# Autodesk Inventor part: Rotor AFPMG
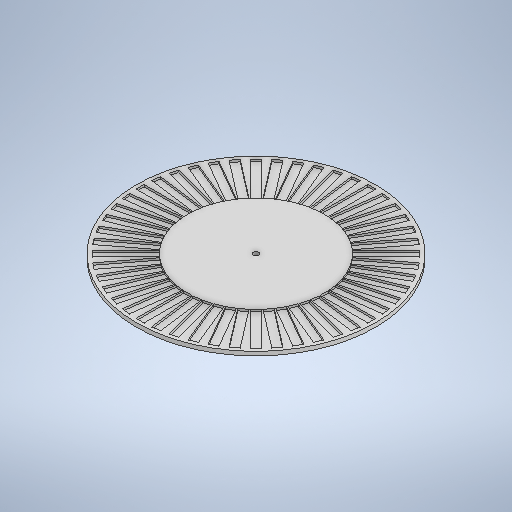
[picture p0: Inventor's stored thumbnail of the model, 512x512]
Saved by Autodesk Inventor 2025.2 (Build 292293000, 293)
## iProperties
Created: 2025-03
Part Number: Rotor AFPMG
Material: Generic
Document SubType Name: Modeling
Designer: bensa
Density: 1 g/cm^3
Appearance: Default
Author: bensa
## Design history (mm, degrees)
sketch "Sketch1"
  geometry: C1 r 150 at (0, 0); 1 further point
  constraints: 1 centre point, 1 coincident
  dimensions: "d0" = 300 diameter of C1
extrude "Extrusion1" new body sketch "Sketch1" distance "d1" = 5; taper "d2" = 0 deg
sketch "Sketch2"
  geometry: L1 (-114.512, -15.076)-(116.488, -15.076); L2 (-111.564, -29.894)-(119.436, -29.894); L3 (84.116, 16.117)-(143.603, 23.949); L4 (143.603, 23.949)-(144.908, 14.034); L5 (144.908, 14.034)-(85.421, 6.203); L6 (85.421, 6.203)-(84.116, 16.117); L7 (84.116, 16.117)-(144.908, 14.034); L8 (143.603, 23.949)-(85.421, 6.203); L9 (81.293, 26.959)-(139.248, 42.488); L10 (139.248, 42.488)-(141.836, 32.829); L11 (141.836, 32.829)-(83.881, 17.299); L12 (83.881, 17.299)-(81.293, 26.959); L13 (81.293, 26.959)-(141.836, 32.829); L14 (139.248, 42.488)-(83.881, 17.299); 1 further point
  constraints: 28 end point, 4 parallel, 2 horizontal, 2 perpendicular
  dimensions: "d7" = 60 distance of L3.start L3.end; "d8" = 10 distance of L3.end L4.end; "d9" = 60 distance of L9.start L9.end; "d10" = 10 distance of L9.end L10.end
sketch "Sketch3"
  geometry: L1 (-106.708, -44.2)-(124.292, -44.2); L2 (80.905, 28.1)-(136.338, 51.061); L3 (136.338, 51.061)-(132.511, 60.3); L4 (132.511, 60.3)-(77.078, 37.339); L5 (77.078, 37.339)-(80.905, 28.1); L6 (80.905, 28.1)-(132.511, 60.3); L7 (136.338, 51.061)-(77.078, 37.339); L8 (-100.026, -57.75)-(130.974, -57.75); L9 (76.545, 38.42)-(128.507, 68.42); L10 (128.507, 68.42)-(123.507, 77.08); L11 (123.507, 77.08)-(71.545, 47.08); L12 (71.545, 47.08)-(76.545, 38.42); L13 (76.545, 38.42)-(123.507, 77.08); L14 (128.507, 68.42)-(71.545, 47.08); L15 (-91.632, -70.312)-(139.368, -70.312); L16 (70.876, 48.082)-(118.477, 84.608); L17 (118.477, 84.608)-(112.389, 92.542); L18 (112.389, 92.542)-(64.788, 56.016); L19 (64.788, 56.016)-(70.876, 48.082); L20 (70.876, 48.082)-(112.389, 92.542); L21 (118.477, 84.608)-(64.788, 56.016); L22 (-81.671, -81.671)-(149.329, -81.671); L23 (63.993, 56.922)-(106.42, 99.349); L24 (106.42, 99.349)-(99.349, 106.42); L25 (99.349, 106.42)-(56.922, 63.993); L26 (56.922, 63.993)-(63.993, 56.922); L27 (63.993, 56.922)-(99.349, 106.42); L28 (106.42, 99.349)-(56.922, 63.993); L29 (-70.312, -91.632)-(160.688, -91.632); L30 (48.082, 70.876)-(84.608, 118.477); L31 (84.608, 118.477)-(92.542, 112.389); L32 (92.542, 112.389)-(56.016, 64.788); L33 (56.016, 64.788)-(48.082, 70.876); L34 (48.082, 70.876)-(92.542, 112.389); L35 (84.608, 118.477)-(56.016, 64.788); L36 (-57.75, -100.026)-(173.25, -100.026); L37 (47.08, 71.545)-(77.08, 123.507); L38 (77.08, 123.507)-(68.42, 128.507); L39 (68.42, 128.507)-(38.42, 76.545); L40 (38.42, 76.545)-(47.08, 71.545); L41 (47.08, 71.545)-(68.42, 128.507); L42 (77.08, 123.507)-(38.42, 76.545); L43 (-44.2, -106.708)-(186.8, -106.708); L44 (37.339, 77.078)-(60.3, 132.511); L45 (60.3, 132.511)-(51.061, 136.338); L46 (51.061, 136.338)-(28.1, 80.905); L47 (28.1, 80.905)-(37.339, 77.078); L48 (37.339, 77.078)-(51.061, 136.338); L49 (60.3, 132.511)-(28.1, 80.905); L50 (-29.894, -111.564)-(201.106, -111.564); L51 (17.299, 83.881)-(32.829, 141.836); L52 (32.829, 141.836)-(42.488, 139.248); L53 (42.488, 139.248)-(26.959, 81.293); L54 (26.959, 81.293)-(17.299, 83.881); L55 (17.299, 83.881)-(42.488, 139.248); L56 (32.829, 141.836)-(26.959, 81.293); L57 (-15.076, -114.512)-(215.924, -114.512); L58 (6.203, 85.421)-(14.034, 144.908); L59 (14.034, 144.908)-(23.949, 143.603); L60 (23.949, 143.603)-(16.117, 84.116); L61 (16.117, 84.116)-(6.203, 85.421); L62 (6.203, 85.421)-(23.949, 143.603); L63 (14.034, 144.908)-(16.117, 84.116); L64 (5, 85.5)-(5, 145.5)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; C1 r 150 at (0, 0); C2 r 150 at (0, 0); A1 r 150 centre (0, 0) between (150, 0) and (-150, 0) reference; 10 further points
  constraints: 328 end point, 32 parallel, 26 midpoint, 16 perpendicular, 12 horizontal, 2 centre point, 1 collinear, 1 point on circle, 2 other
  dimensions: "d13" = 60 distance of L2.start L2.end; "d14" = 10 distance of L3.end L2.end; "d17" = 60 distance of L9.start L9.end; "d18" = 10 distance of L10.end L9.end; "d21" = 60 distance of L16.start L16.end; "d22" = 10 distance of L17.end L16.end; "d25" = 60 distance of L23.start L23.end; "d26" = 10 distance of L24.end L23.end; "d29" = 60 distance of L30.start L30.end; "d30" = 10 distance of L30.end L31.end; "d33" = 60 distance of L37.start L37.end; "d34" = 10 distance of L38.end L37.end; "d37" = 60 distance of L44.start L44.end; "d38" = 10 distance of L45.end L44.end; "d41" = 60 distance of L51.start L51.end; "d42" = 10 distance of L51.end L52.end; "d45" = 60 distance of L58.start L58.end; "d46" = 10 distance of L58.end L59.end; "d48" = 60 distance of L64.start L64.end; "d49" = 10 distance of L65.end L64.end; "d52" = 60 distance of L126.start L126.end; "d53" = 10 distance of L127.end L126.end; "d56" = 60 distance of L133.start L133.end; "d57" = 10 distance of L133.end L134.end; "d59" = 60 distance of L140.start L140.end; "d60" = 10 distance of L140.end L141.end; "d61" = 60 distance of L147.start L147.end; "d62" = 10 distance of L148.end L147.end; "d63" = 60 distance of L153.start L153.end; "d64" = 10 distance of L153.end L154.end; "d65" = 60 distance of L159.start L159.end; "d66" = 10 distance of L159.end L160.end
sketch "Sketch4"
  geometry: L1 (0, 0)-(115.5, 0); L2 (-143.603, -23.949)-(-84.116, -16.117); L3 (-84.116, -16.117)-(-85.421, -6.203); L4 (-85.421, -6.203)-(-144.908, -14.034); L5 (-144.908, -14.034)-(-143.603, -23.949); L6 (-143.603, -23.949)-(-85.421, -6.203); L7 (-84.116, -16.117)-(-144.908, -14.034); L8 (0, 0)-(115.5, 0); L9 (-141.836, -32.829)-(-83.881, -17.299); L10 (-83.881, -17.299)-(-81.293, -26.959); L11 (-81.293, -26.959)-(-139.248, -42.488); L12 (-139.248, -42.488)-(-141.836, -32.829); L13 (-141.836, -32.829)-(-81.293, -26.959); L14 (-83.881, -17.299)-(-139.248, -42.488); L15 (0, 0)-(115.5, 0); L16 (-136.338, -51.061)-(-80.905, -28.1); L17 (-80.905, -28.1)-(-77.078, -37.339); L18 (-77.078, -37.339)-(-132.511, -60.3); L19 (-132.511, -60.3)-(-136.338, -51.061); L20 (-136.338, -51.061)-(-77.078, -37.339); L21 (-80.905, -28.1)-(-132.511, -60.3); L22 (0, 0)-(115.5, 0); L23 (-123.507, -77.08)-(-71.545, -47.08); L24 (-71.545, -47.08)-(-76.545, -38.42); L25 (-76.545, -38.42)-(-128.507, -68.42); L26 (-128.507, -68.42)-(-123.507, -77.08); L27 (-123.507, -77.08)-(-76.545, -38.42); L28 (-71.545, -47.08)-(-128.507, -68.42); L29 (0, 0)-(115.5, 0); L30 (-112.389, -92.542)-(-64.788, -56.016); L31 (-64.788, -56.016)-(-70.876, -48.082); L32 (-70.876, -48.082)-(-118.477, -84.608); L33 (-118.477, -84.608)-(-112.389, -92.542); L34 (-112.389, -92.542)-(-70.876, -48.082); L35 (-64.788, -56.016)-(-118.477, -84.608); L36 (0, 0)-(115.5, 0); L37 (-106.42, -99.349)-(-63.993, -56.922); L38 (-63.993, -56.922)-(-56.922, -63.993); L39 (-56.922, -63.993)-(-99.349, -106.42); L40 (-99.349, -106.42)-(-106.42, -99.349); L41 (-106.42, -99.349)-(-56.922, -63.993); L42 (-63.993, -56.922)-(-99.349, -106.42); L43 (0, 0)-(115.5, 0); L44 (-92.542, -112.389)-(-56.016, -64.788); L45 (-56.016, -64.788)-(-48.082, -70.876); L46 (-48.082, -70.876)-(-84.608, -118.477); L47 (-84.608, -118.477)-(-92.542, -112.389); L48 (-92.542, -112.389)-(-48.082, -70.876); L49 (-56.016, -64.788)-(-84.608, -118.477); L50 (0, 0)-(115.5, 0); L51 (-77.08, -123.507)-(-47.08, -71.545); L52 (-47.08, -71.545)-(-38.42, -76.545); L53 (-38.42, -76.545)-(-68.42, -128.507); L54 (-68.42, -128.507)-(-77.08, -123.507); L55 (-77.08, -123.507)-(-38.42, -76.545); L56 (-47.08, -71.545)-(-68.42, -128.507); L57 (0, 0)-(115.5, 0); L58 (-60.3, -132.511)-(-37.339, -77.078); L59 (-37.339, -77.078)-(-28.1, -80.905); L60 (-28.1, -80.905)-(-51.061, -136.338); L61 (-51.061, -136.338)-(-60.3, -132.511); L62 (-60.3, -132.511)-(-28.1, -80.905); L63 (-37.339, -77.078)-(-51.061, -136.338); L64 (0, 0)-(115.5, 0)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
  constraints: 282 end point, 42 parallel, 21 perpendicular, 15 horizontal
  dimensions: "d69" = 60 distance of L2.start L2.end; "d70" = 10 distance of L3.end L2.end; "d73" = 60 distance of L9.start L9.end; "d74" = 10 distance of L9.end L10.end; "d77" = 60 distance of L16.start L16.end; "d78" = 10 distance of L16.end L17.end; "d81" = 60 distance of L23.start L23.end; "d82" = 10 distance of L24.end L23.end; "d85" = 60 distance of L30.start L30.end; "d86" = 10 distance of L31.end L30.end; "d89" = 60 distance of L37.start L37.end; "d90" = 10 distance of L37.end L38.end; "d93" = 60 distance of L44.start L44.end; "d94" = 10 distance of L44.end L45.end; "d97" = 60 distance of L51.start L51.end; "d98" = 10 distance of L51.end L52.end; "d101" = 60 distance of L58.start L58.end; "d102" = 10 distance of L58.end L59.end; "d105" = 60 distance of L65.start L65.end; "d106" = 10 distance of L66.end L65.end; "d109" = 60 distance of L72.start L72.end; "d110" = 10 distance of L72.end L73.end; "d112" = 60 distance of L78.start L78.end; "d113" = 10 distance of L79.end L78.end; "d116" = 60 distance of L85.start L85.end; "d117" = 10 distance of L85.end L86.end; "d119" = 60 distance of L91.start L91.end; "d120" = 10 distance of L92.end L91.end; "d122" = 60 distance of L97.start L97.end; "d123" = 10 distance of L98.end L97.end; "d126" = 60 distance of L104.start L104.end; "d127" = 10 distance of L104.end L105.end; "d130" = 60 distance of L111.start L111.end; "d131" = 10 distance of L112.end L111.end; "d133" = 60 distance of L117.start L117.end; "d134" = 10 distance of L117.end L118.end; "d137" = 60 distance of L124.start L124.end; "d138" = 10 distance of L125.end L124.end; "d140" = 60 distance of L130.start L130.end; "d141" = 10 distance of L130.end L131.end; "d143" = 60 distance of L136.start L136.end; "d144" = 10 distance of L137.end L136.end
extrude "Extrusion2" cut sketch "Sketch3" distance "d145" = 2.6; taper "d146" = 0 deg
extrude "Extrusion3" cut sketch "Sketch2" distance "d147" = 2.6; taper "d148" = 0 deg
extrude "Extrusion4" cut sketch "Sketch4" distance "d149" = 2.6; taper "d150" = 0 deg
sketch "Sketch5"
  geometry: C1 r 3.375 at (0, 0); 1 further point
  constraints: 1 centre point
  dimensions: "d152" = 6.75 diameter of C1
extrude "Extrusion5" cut sketch "Sketch5" distance "d153" = 10; taper "d154" = 0 deg
body "Solid1"
